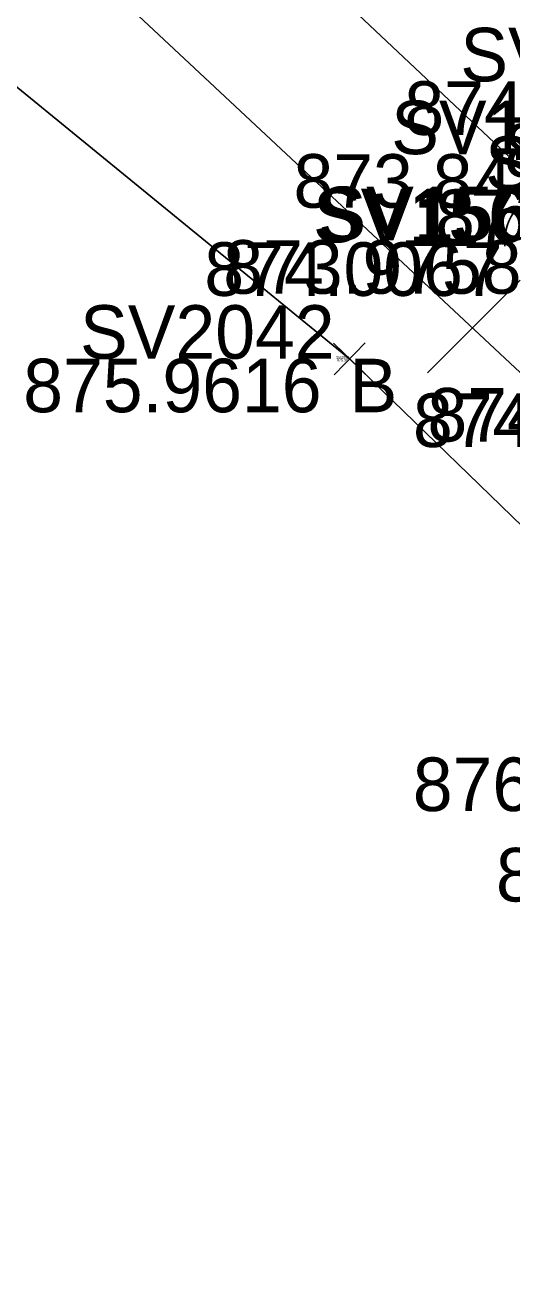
# Model space of a CAD drawing. Extents: x 1469677 to 1493262, y 375219 to 389293.
# Drawn here: x 1480116.52 to 1480127.45, y 379405.99 to 379434.1 of the extents above; entities that cross this region are included whole.
import ezdxf

# ---------------------------------------------------------------- set-up
doc = ezdxf.new("R2010")
doc.units = 0
for name, color, linetype in [('DV_X_Lot_Line', 7, 'Continuous'), ('DV_X_Text', 7, 'Continuous'), ('GK_Visualization', 7, 'Continuous'), ('PNTELEV', 7, 'Continuous'), ('PNTNO', 7, 'Continuous'), ('RW_P_Esmt_SW', 7, 'Continuous'), ('SV_X_Mon_Cells_Found', 7, 'Continuous'), ('text', 7, 'Continuous')]:
    doc.layers.add(name, color=color, linetype=linetype)

msp = doc.modelspace()

# ---------------------------------------------------------------- linework, layer by layer
at = {"layer": 'DV_X_Lot_Line'}
msp.add_lwpolyline([(1480035.484, 379289.224), (1480050.568, 379305.437), (1480062.335, 379317.896), (1480064.038, 379319.719), (1480070.805, 379327.066), (1480078.054, 379334.946), (1480079.953, 379336.866), (1480094.208, 379352.393), (1480112.048, 379371.575), (1480117.348, 379377.211), (1480119.911, 379379.906), (1480121.511, 379381.77), (1480134.604, 379395.58), (1480136.695, 379398.148), (1480138.778, 379401.149), (1480140.004, 379404.725), (1480140.577, 379408.06), (1480140.982, 379411.311), (1480140.871, 379414.584), (1480140.225, 379417.636), (1480139.184, 379419.586), (1480133.124, 379425.845), (1480132.903, 379425.968), (1480114.834, 379442.96)], dxfattribs=at)
at = {"layer": 'PNTELEV'}
for p, q in [((1480124.162, 379426.276), (1480123.444, 379426.972)), ((1480123.455, 379426.265), (1480124.151, 379426.983)), ((1480123.803, 379426.624), (1480123.803, 379426.624))]:
    msp.add_line(p, q, dxfattribs=at)
at = {"layer": 'PNTNO'}
for p, q in [((1480129.678, 379431.298), (1480127.278, 379431.298)), ((1480127.633, 379428.386), (1480125.553, 379426.308))]:
    msp.add_line(p, q, dxfattribs=at)
msp.add_arc((1480128.48, 379429.234), 1.2, 140.021, 184.0629, dxfattribs=at)
at = {"layer": 'SV_X_Mon_Cells_Found'}
msp.add_lwpolyline([(1477164.629, 382297.849), (1479615.888, 379904.59), (1480413.414, 379159.216)], dxfattribs=at)
at = {"layer": 'text'}
msp.add_lwpolyline([(1480127.721, 379395.358), (1480131.799, 379398.039), (1480133.273, 379401.352), (1480135.459, 379407.36), (1480135.6, 379409.555), (1480135.793, 379413.076), (1480135.014, 379415.657), (1480133.026, 379417.684), (1480123.803, 379426.624), (1480113.121, 379435.343), (1480106.984, 379440.926), (1480103.73, 379443.918), (1480102.529, 379445.074), (1480100.774, 379445.951), (1480096.595, 379444.059), (1480092.174, 379441.029), (1480086.377, 379436.591)], dxfattribs=at)

# ---------------------------------------------------------------- texts
at = {"layer": 'DV_X_Text'}
for s, height, p in [('874.1312', 1.2, (1480125.032, 379431.643)), ('873.8959', 1.2, (1480127.271, 379430.697)), ('873.8478', 1.2, (1480122.545, 379430.01)), ('873.9381', 1.2, (1480125.723, 379429.213)), ('873.9758', 1.2, (1480120.969, 379428.082)), ('874.0067', 1.2, (1480120.544, 379428.034)), ('875.9616', 1.2, (1480116.481, 379425.424)), ('875.96', 0.06, (1480123.518, 379426.564)), ('874.0321', 1.2, (1480125.55, 379424.768)), ('874.0075', 1.2, (1480125.225, 379424.645)), ('876.0884', 1.2, (1480125.222, 379416.484)), ('876.0840', 1.2, (1480127.087, 379414.457))]:
    msp.add_text(s, height=height, dxfattribs=at).set_placement(p)
at = {"layer": 'GK_Visualization'}
msp.add_text('B', height=1.2, dxfattribs=at).set_placement((1480123.803, 379425.424))
at = {"layer": 'RW_P_Esmt_SW'}
for s, height, p in [('SV1565', 1.2, (1480126.288, 379432.843)), ('SV1568', 1.2, (1480124.737, 379431.21)), ('SV2008', 1.2, (1480126.84, 379430.413)), ('SV1567', 1.2, (1480122.982, 379429.234)), ('SV1566', 1.2, (1480123.105, 379429.282)), ('SV2042', 1.2, (1480117.756, 379426.624)), ('SV2042', 0.06, (1480123.501, 379426.624))]:
    msp.add_text(s, height=height, dxfattribs=at).set_placement(p)

doc.saveas('drawing.dxf')
